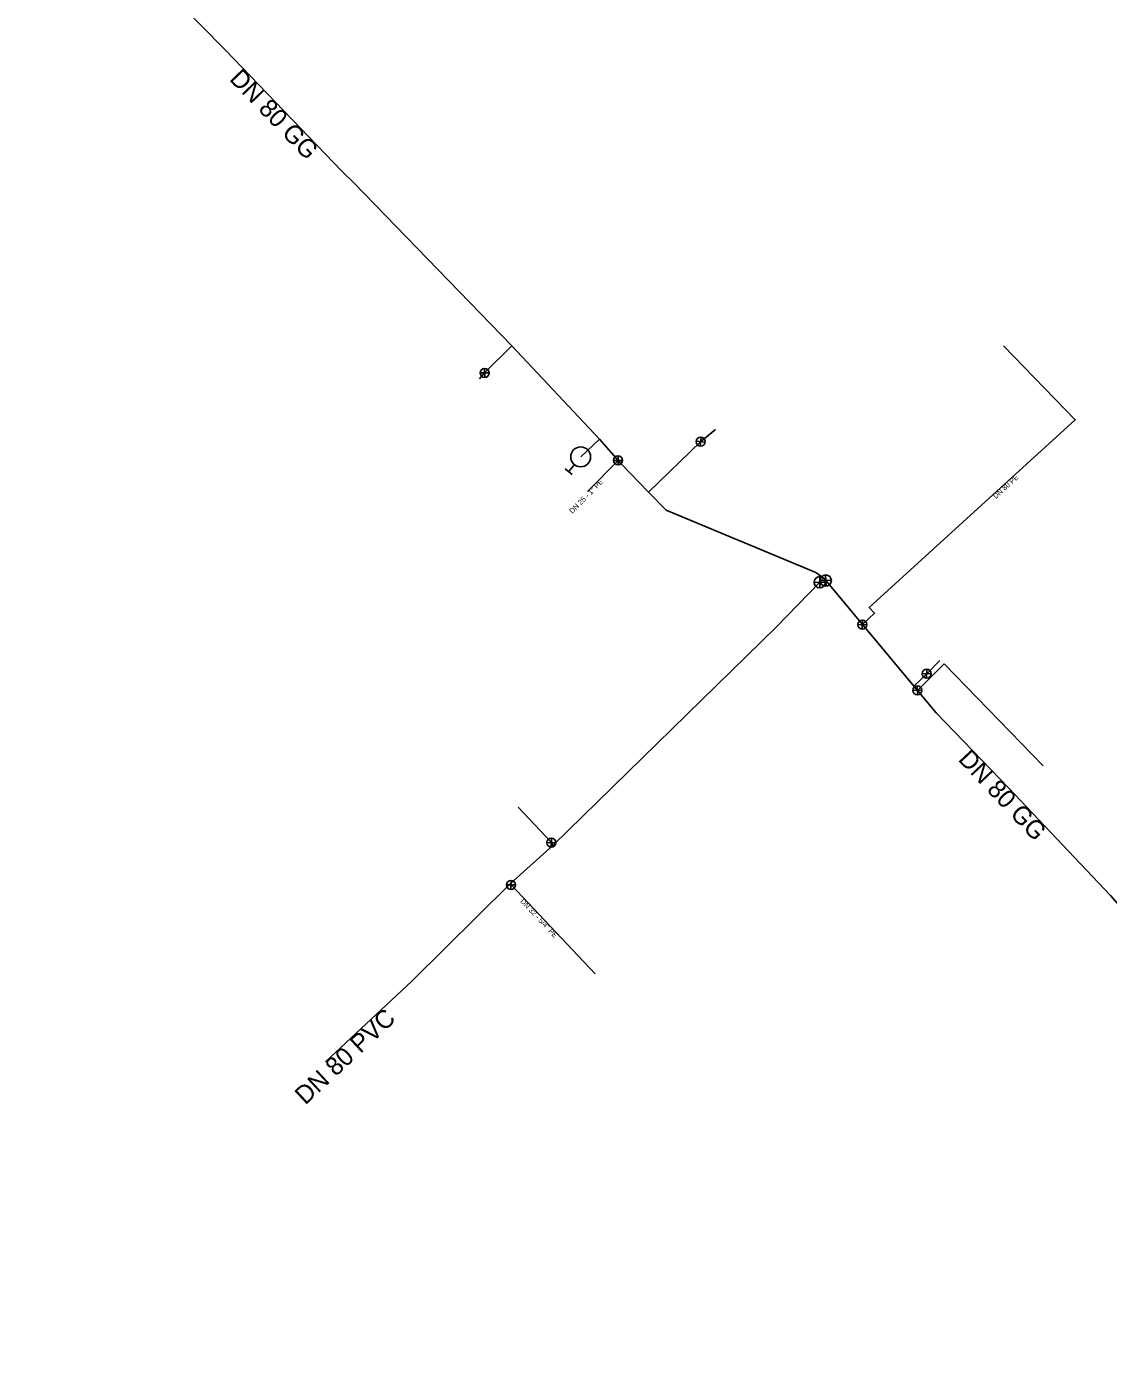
# Model space of a CAD drawing. Extents: x -446879 to -446633, y -1113504 to -1113264.
# Drawn here: x -446878.7 to -446782.8, y -1113499.8 to -1113382.1 of the extents above; entities that cross this region are included whole.
import ezdxf

# ---------------------------------------------------------------- set-up
doc = ezdxf.new("R2010")
doc.units = 0
for name, color, linetype in [('_hydrantova_odbocka_', 7, 'Continuous'), ('_pripojka_prevzato_z_dokumentace_', 7, 'Continuous'), ('_pripojka_priblizne_', 7, 'Continuous'), ('_voda_smvak_prevzato_z_dokumentace_', 7, 'Continuous'), ('Default', 7, 'Continuous'), ('MoLevel 27', 7, 'Continuous'), ('MoLevel 28', 7, 'Continuous'), ('MoLevel 32', 7, 'Continuous'), ('MoLevel 46', 7, 'Continuous'), ('MoLevel 53', 7, 'Continuous')]:
    doc.layers.add(name, color=color, linetype=linetype)

# ---------------------------------------------------------------- blocks, each defined once
blk = doc.blocks.new('_uzaver_')
at = {"layer": 'Default'}
for p, q in [((-0.000035, -0.000035), (0.000035, 0.000035)), ((0.000035, -0.000035), (-0.000035, 0.000035))]:
    blk.add_line(p, q, dxfattribs=at)
for radius in [0.00005, 0.0000025]:
    blk.add_circle((0, 0), radius, dxfattribs=at)
blk = doc.blocks.new('_uzaver_pripojka_')
at = {"layer": 'Default'}
for p, q in [((-0.000035, -0.000035), (0.000035, 0.000035)), ((0.000035, -0.000035), (-0.000035, 0.000035))]:
    blk.add_line(p, q, dxfattribs=at)
for radius in [0.00005, 0.0000025]:
    blk.add_circle((0, 0), radius, dxfattribs=at)
blk = doc.blocks.new('_hydrant_voda_')
at = {"layer": 'Default'}
for p, q in [((-0.0000225, 0.000095), (0.0000225, 0.000095)), ((0, 0.000095), (0, 0.00005))]:
    blk.add_line(p, q, dxfattribs=at)
blk.add_circle((0, 0), 0.00005, dxfattribs=at)

msp = doc.modelspace()

# ---------------------------------------------------------------- linework, layer by layer
at = {"layer": '_hydrantova_odbocka_'}
msp.add_line((-446827.89, -1113418.6), (-446829.57, -1113420.17), dxfattribs=at)
at = {"layer": '_pripojka_prevzato_z_dokumentace_'}
msp.add_line((-446797.38, -1113438.49), (-446788.61, -1113447.55), dxfattribs=at)
at = {"layer": '_pripojka_priblizne_'}
for p, q in [((-446826.26, -1113420.48), (-446828.98, -1113423.23)), ((-446799.74, -1113440.85), (-446797.38, -1113438.49))]:
    msp.add_line(p, q, dxfattribs=at)
for points in [[(-446835.66, -1113410.34), (-446838.08, -1113412.73), (-446838.53, -1113413.25)], [(-446804.61, -1113435.03), (-446803.53, -1113434.01), (-446804, -1113433.52), (-446785.76, -1113416.88), (-446792.1, -1113410.32)], [(-446823.56, -1113423.3), (-446818.94, -1113418.82), (-446817.64, -1113417.73)], [(-446800.05, -1113440.48), (-446798.91, -1113439.38), (-446797.74, -1113438.2)], [(-446832, -1113454.57), (-446832.16, -1113454.34), (-446835.11, -1113451.21)], [(-446835.82, -1113457.98), (-446835.74, -1113458.08), (-446828.29, -1113465.97)]]:
    msp.add_lwpolyline(points, dxfattribs=at)
at = {"layer": '_voda_smvak_prevzato_z_dokumentace_'}
for p in [(-446808.39, -1113431.28), (-446807.86, -1113431.13)]:
    msp.add_line(p, (-446808.07, -1113430.92), dxfattribs=at)
for points in [[(-446827.89, -1113418.6), (-446835.66, -1113410.34), (-446849.67, -1113395.89), (-446850.69, -1113394.88), (-446861.08, -1113384.12), (-446878.66, -1113366.24)], [(-446808.07, -1113430.92), (-446808.74, -1113430.4), (-446821.99, -1113424.88), (-446823.56, -1113423.3), (-446825.99, -1113420.79), (-446827.89, -1113418.6)], [(-446852.17, -1113473.75), (-446844.53, -1113466.62), (-446835.82, -1113457.98), (-446832, -1113454.57), (-446812.24, -1113435.26), (-446808.39, -1113431.28)], [(-446743.69, -1113499.76), (-446747.47, -1113495.83), (-446764.41, -1113478.5), (-446775.92, -1113466.68), (-446782.64, -1113459.03), (-446791.63, -1113449.52), (-446798.08, -1113442.84), (-446807.86, -1113431.13)]]:
    msp.add_lwpolyline(points, dxfattribs=at)

# ---------------------------------------------------------------- block references
at = {"layer": 'MoLevel 27', "xscale": 10000}
for p, yscale, rotation in [((-446807.86, -1113431.13), 9999.999999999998, -42.07678755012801), ((-446808.39, -1113431.28), 10000, -134.042536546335)]:
    msp.add_blockref('_uzaver_', p, dxfattribs=dict(at, yscale=yscale, rotation=rotation))
at = {"layer": 'MoLevel 28', "xscale": 17636.68430335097, "yscale": 17636.684303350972, "rotation": 140.782392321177}
msp.add_blockref('_hydrant_voda_', (-446829.57, -1113420.17), dxfattribs=at)
at = {"layer": 'MoLevel 53'}
for p, xscale, yscale, rotation in [((-446838.08, -1113412.73), 7999.999999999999, 8000.000000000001, -134.55585556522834), ((-446818.94, -1113418.82), 7999.999999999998, 8000, 40.17923392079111), ((-446826.26, -1113420.48), 7999.999999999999, 8000, -134.7074292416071), ((-446804.61, -1113435.03), 7999.999999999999, 7999.999999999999, 42.3727137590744), ((-446798.91, -1113439.38), 7999.999999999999, 7999.999999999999, 43.00543069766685), ((-446799.74, -1113440.85), 7999.999999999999, 7999.999999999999, 46.41461780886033), ((-446832.16, -1113454.34), 7999.999999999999, 7999.999999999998, 132.939888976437), ((-446835.74, -1113458.08), 8000, 8000, -46.629724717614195)]:
    msp.add_blockref('_uzaver_pripojka_', p, dxfattribs=dict(at, xscale=xscale, yscale=yscale, rotation=rotation))

# ---------------------------------------------------------------- texts
at = {"layer": 'MoLevel 32'}
for s, rotation, p in [('DN 80 PE', 42.3729, (-446792.79, -1113423.91)), ("DN 25 - 1'' PE", 45.2926, (-446830.31, -1113425.22)), ("DN 32 - 5/4'' PE", 313.3703, (-446834.96, -1113459.57))]:
    msp.add_text(s, height=0.455, rotation=rotation, dxfattribs=at).set_placement(p)
at = {"layer": 'MoLevel 46'}
for s, rotation, p in [('DN 80 GG', 313.9978, (-446860.77, -1113386.76)), ('DN 80 GG', 313.3772, (-446796.2, -1113447.02)), ('DN 80 PVC', 43.0224, (-446853.97, -1113477.63))]:
    msp.add_text(s, height=1.605, rotation=rotation, dxfattribs=at).set_placement(p)

doc.saveas('drawing.dxf')
